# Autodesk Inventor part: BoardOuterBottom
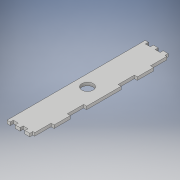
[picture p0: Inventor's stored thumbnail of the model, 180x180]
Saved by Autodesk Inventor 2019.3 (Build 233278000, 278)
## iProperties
Created: 2020-03
Part Number: BoardOuterBottom
Material: Generic
Document SubType Name: Modeling
Designer: KrystynWikoff
Density: 1 g/cm^3
Appearance: Default
Author: KrystynWikoff
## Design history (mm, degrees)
sketch "Sketch1"
  geometry: L1 (0, 0)-(21.59, 0); L2 (21.59, 0)-(21.59, -107.824); L3 (21.59, -107.824)-(0, -107.824); L4 (0, -107.824)-(0, 0)
  constraints: 8 end point, 2 parallel, 1 horizontal, 1 perpendicular
  dimensions: "d0" = 107.8244 distance of L3.end L1.start; "d1" = 21.59 distance of L1.start L1.end
extrude "Extrusion1" new body sketch "Sketch1" distance "d2" = 2.3622; taper "d3" = 0 deg
sketch "Sketch2" dims "d11" = 25.4, "d22" = 25.4
  geometry: L1 (0, 0)-(-3.81, 0); L2 (-3.81, 0)-(-3.81, 2.362); L3 (-3.81, 2.362)-(0, 2.362); L4 (0, 2.362)-(0, 0); L5 (-7.62, 0)-(-11.43, 0); L6 (-11.43, 0)-(-11.43, 2.362); L7 (-11.43, 2.362)-(-7.62, 2.362); L8 (-7.62, 2.362)-(-7.62, 0); L9 (-15.24, 0)-(-19.05, 0); L10 (-19.05, 0)-(-19.05, 2.362); L11 (-19.05, 2.362)-(-15.24, 2.362); L12 (-15.24, 2.362)-(-15.24, 0); L13 (0, 107.824)-(-3.81, 107.824); L14 (-3.81, 107.824)-(-3.81, 105.462); L15 (-3.81, 105.462)-(0, 105.462); L16 (0, 105.462)-(0, 107.824); L17 (0, 107.824)-(-21.59, 107.824) reference; L18 (0, 0)-(0, 107.824) reference; L19 (-11.43, 105.462)-(-7.62, 105.462); L20 (-11.43, 107.824)-(-11.43, 105.462); L21 (-7.62, 105.462)-(-7.62, 107.824); L22 (-7.62, 107.824)-(-11.43, 107.824); L23 (-19.05, 105.462)-(-15.24, 105.462); L24 (-19.05, 107.824)-(-19.05, 105.462); L25 (-15.24, 105.462)-(-15.24, 107.824); L26 (-15.24, 107.824)-(-19.05, 107.824)
  constraints: 48 end point, 4 horizontal, 4 parallel, 2 perpendicular, 1 collinear, 31 other
  dimensions: "d4" = 3.81 distance of L2.end L3.end; "d5" = 2.3622 distance of L3.end L1.start; "d8" = 7.62 distance of L2.end L6.end; "d13" = 3.81 distance of L14.end L15.end; "d14" = 2.3622 distance of L13.end L14.end; "d15" = 0 distance between parallel lines of L17 L13; "d16" = 0 distance between parallel lines of L18 L16; "d19" = 7.62 distance of L15.end L19.end
extrude "Extrusion2" cut sketch "Sketch2" distance "d24" = 2.3622; taper "d25" = 0 deg
sketch "Sketch3" dims "d33" = 25.4, "d42" = 25.4
  geometry: L1 (0, 105.462)-(0, 2.362) reference; L2 (0, 2.362)-(-2.362, 2.362); L3 (-2.362, 2.362)-(-2.362, 15.062); L4 (-2.362, 15.062)-(0, 15.062); L5 (0, 15.062)-(0, 2.362); L6 (0, 27.762)-(-2.362, 27.762); L7 (-2.362, 27.762)-(-2.362, 40.462); L8 (-2.362, 40.462)-(0, 40.462); L9 (0, 40.462)-(0, 27.762); L10 (0, 105.462)-(-2.362, 105.462); L11 (-2.362, 105.462)-(-2.362, 92.762); L12 (-2.362, 92.762)-(0, 92.762); L13 (0, 92.762)-(0, 105.462); L14 (0, 80.062)-(-2.362, 80.062); L15 (-2.362, 80.062)-(-2.362, 67.362); L16 (-2.362, 67.362)-(0, 67.362); L17 (0, 67.362)-(0, 80.062); 1 further point
  constraints: 32 end point, 4 parallel, 2 horizontal, 2 perpendicular, 2 vertical, 16 other
  dimensions: "d26" = 12.7 distance of L2.end L3.end; "d27" = 2.3622 distance of L3.end L4.end; "d30" = 25.4 distance of L3.end L7.end; "d35" = 12.7 distance of L10.end L11.end; "d36" = 2.3622 distance of L11.end L12.end; "d39" = 25.4 distance of L11.end L15.end
extrude "Extrusion3" cut sketch "Sketch3" distance "d44" = 2.3622; taper "d45" = 0 deg
sketch "Sketch4"
  geometry: L1 (0, 40.462)-(0, 67.362) reference; L2 (-11.43, 107.824)-(-15.24, 107.824) reference; C1 r 4.445 at (-12.7, 53.913); 1 further point
  constraints: 1 centre point
  dimensions: "d46" = 8.89 diameter of C1; "d47" = 12.7 distance from line of L1 C1.centre; "d48" = 53.9115 distance from line of L2 C1.centre
extrude "Extrusion4" cut sketch "Sketch4" distance "d49" = 25.4; taper "d50" = 0 deg
body "Solid1"
